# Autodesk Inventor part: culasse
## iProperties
Created: 2011-09
Part Number: culasse
Document SubType Name: Modeling
Designer: Dominique
Author: Dominique
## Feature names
1. Extrusion1
2. Extrusion2
3. Extrusion3
4. Perçage1 [Hole]
5. Extrusion4
